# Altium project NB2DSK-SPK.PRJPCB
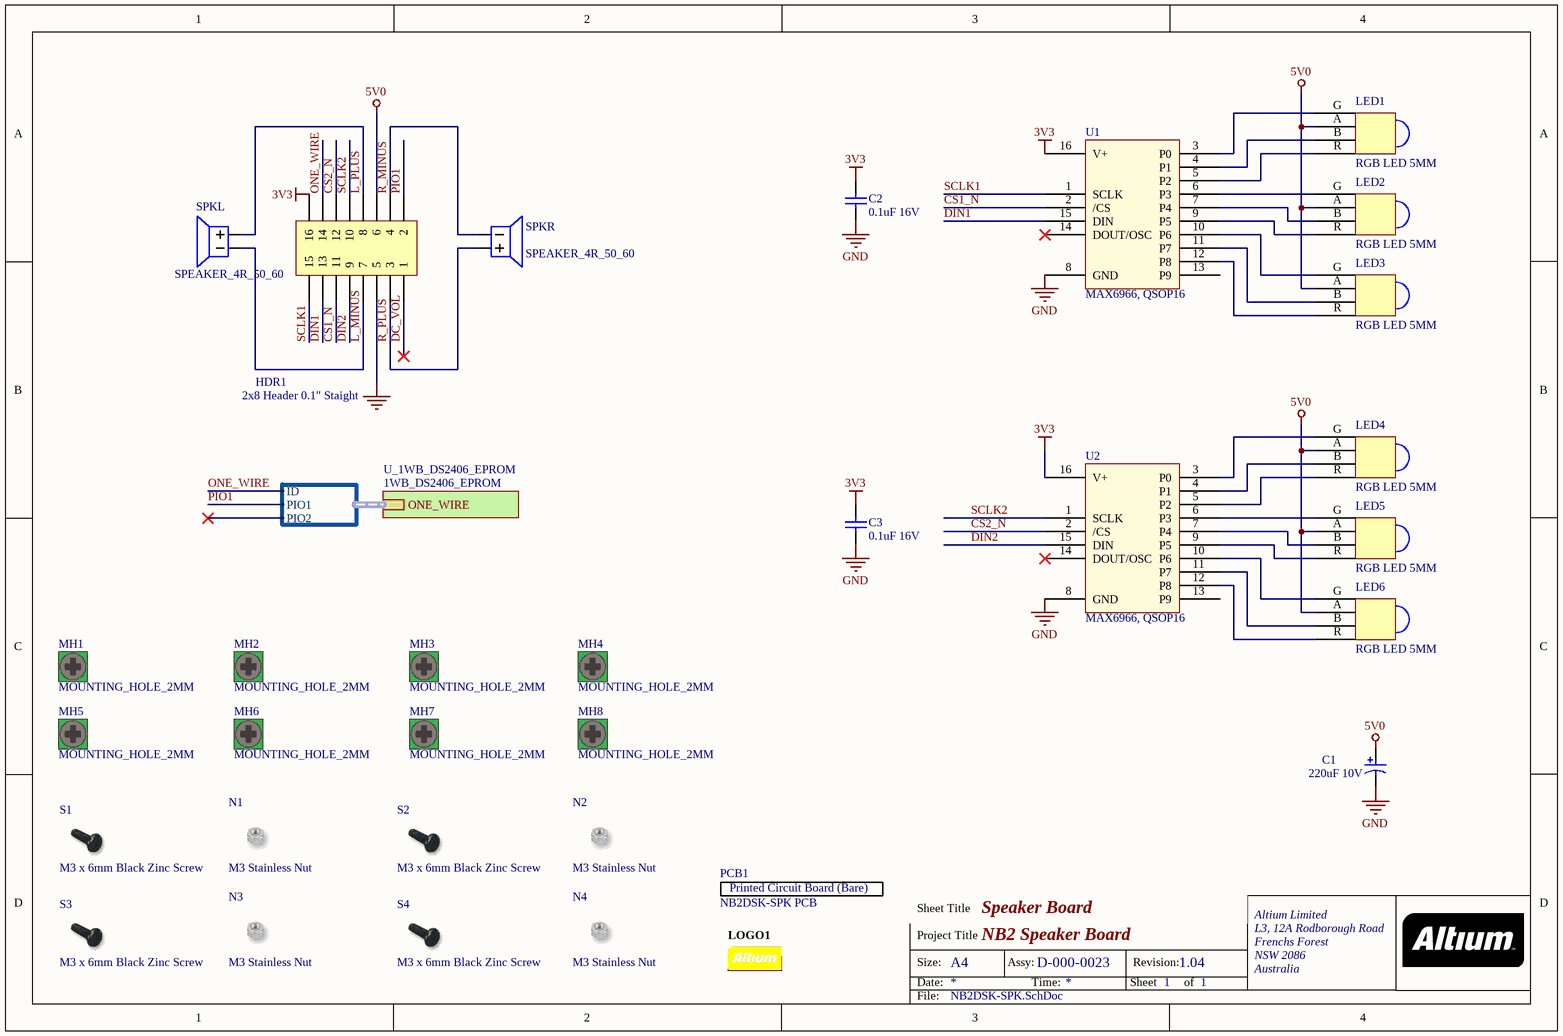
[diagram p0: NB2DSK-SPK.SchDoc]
ProjectAddress1: L3, 12A Rodborough Road; ProjectAddress2: Frenchs Forest; ProjectAddress3: NSW 2086; ProjectAddress4: Australia; ProjectAssyNum: D-000-0023; ProjectOrganization: Altium Limited; ProjectRevision: 1.04; ProjectTitle: NB2 Speaker Board; ProjectTotalSheets: 1
1 sheet, 32 parts. Net scope: hierarchical (ports join the sheet entries above them; power ports are global).
Board file: NB2DSK-SPK.PcbDoc

## Sheet NB2DSK-SPK.SchDoc: Speaker Board
size A4; SheetNumber: 1; SheetTotal: 1; PageSetup: Record=PageOptions|CenterHorizontal=True|CenterVertical=True|PrintScale=0.97|XCorrection=1.00|YCorrection=1.00|PrintKind=1|BorderSize=5000000|LeftOffset=0|BottomOffset=0|Orientation=2|PaperLength=1000|PaperWidth=1000|Scale=100|PaperSource=7|PrintQuality=-4|MediaType=1|DitherType=10|PaperKind=A4 (210 x 297 mm)|PrintScaleMode=1

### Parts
C1  220uF 10V  [CAPC7343-STAR]
C2  0.1uF 16V  [CAPC1005-STAR]
C3  0.1uF 16V  [CAPC1005-STAR]
HDR1  2x8 Header 0.1" Staight  [HDR2X8]
LED1  RGB LED 5MM  [LED-RGB-5MM-RA]
LED2  RGB LED 5MM  [LED-RGB-5MM-RA]
LED3  RGB LED 5MM  [LED-RGB-5MM-RA]
LED4  RGB LED 5MM  [LED-RGB-5MM-RA]
LED5  RGB LED 5MM  [LED-RGB-5MM-RA]
LED6  RGB LED 5MM  [LED-RGB-5MM-RA]
LOGO1  Altium  [Logo-Altium]  (value not drawn)  (no BOM)
MH1  MOUNTING_HOLE_2MM  [MOUNTING_HOLE_2MM]  (no BOM)
MH2  MOUNTING_HOLE_2MM  [MOUNTING_HOLE_2MM]  (no BOM)
MH3  MOUNTING_HOLE_2MM  [MOUNTING_HOLE_2MM]  (no BOM)
MH4  MOUNTING_HOLE_2MM  [MOUNTING_HOLE_2MM]  (no BOM)
MH5  MOUNTING_HOLE_2MM  [MOUNTING_HOLE_2MM]  (no BOM)
MH6  MOUNTING_HOLE_2MM  [MOUNTING_HOLE_2MM]  (no BOM)
MH7  MOUNTING_HOLE_2MM  [MOUNTING_HOLE_2MM]  (no BOM)
MH8  MOUNTING_HOLE_2MM  [MOUNTING_HOLE_2MM]  (no BOM)
N1  M3 Stainless Nut  (mechanical)
N2  M3 Stainless Nut  (mechanical)
N3  M3 Stainless Nut  (mechanical)
N4  M3 Stainless Nut  (mechanical)
PCB1  NB2DSK-SPK PCB  (mechanical)
S1  M3 x 6mm Black Zinc Screw  (mechanical)
S2  M3 x 6mm Black Zinc Screw  (mechanical)
S3  M3 x 6mm Black Zinc Screw  (mechanical)
S4  M3 x 6mm Black Zinc Screw  (mechanical)
SPKL  SPEAKER_4R_50_60  [SPEAKER_4R_50_60]
SPKR  SPEAKER_4R_50_60  [SPEAKER_4R_50_60]
U1  MAX6966, QSOP16  [QSOP16]
U2  MAX6966, QSOP16  [QSOP16]

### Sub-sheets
U_1WB_DS2406_EPROM = 1WB_DS2406_EPROM (file not in this document): ONE_WIRE (harness ONE_WIRE)

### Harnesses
ONE_WIRE: ID, PIO2, PIO1

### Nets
3V3: C2.2 C3.2 HDR1.16 U1.16(V+) U2.16(V+)
5V0: C1.1 HDR1.6 LED1.A LED2.A LED3.A LED4.A LED5.A LED6.A
GND: C1.2 C2.1 C3.1 HDR1.5 U1.8(GND) U2.8(GND)
CS1_N: HDR1.11 U1.2(/CS)
CS2_N: HDR1.12 U2.2(/CS)
DC_VOL: HDR1.1
DIN1: HDR1.13 U1.15(DIN)
DIN2: HDR1.9 U2.15(DIN)
L_MINUS: HDR1.7 SPKL.2
L_PLUS: HDR1.8 SPKL.1
ONE_WIRE: HDR1.14 ; sheet U_1WB_DS2406_EPROM/ONE_WIRE.ID
PIO1: HDR1.2 ; sheet U_1WB_DS2406_EPROM/ONE_WIRE.PIO1
R_MINUS: HDR1.4 SPKR.2
R_PLUS: HDR1.3 SPKR.1
SCLK1: HDR1.15 U1.1(SCLK)
SCLK2: HDR1.10 U2.1(SCLK)
NetLED1_B: LED1.B U1.4(P1)
NetLED1_G: LED1.G U1.3(P0)
NetLED1_R: LED1.R U1.5(P2)
NetLED2_B: LED2.B U1.7(P4)
NetLED2_G: LED2.G U1.6(P3)
NetLED2_R: LED2.R U1.9(P5)
NetLED3_B: LED3.B U1.11(P7)
NetLED3_G: LED3.G U1.10(P6)
NetLED3_R: LED3.R U1.12(P8)
NetLED4_B: LED4.B U2.4(P1)
NetLED4_G: LED4.G U2.3(P0)
NetLED4_R: LED4.R U2.5(P2)
NetLED5_B: LED5.B U2.7(P4)
NetLED5_G: LED5.G U2.6(P3)
NetLED5_R: LED5.R U2.9(P5)
NetLED6_B: LED6.B U2.11(P7)
NetLED6_G: LED6.G U2.10(P6)
NetLED6_R: LED6.R U2.12(P8)

Not connected (* = marked no-connect by the designer): MH1 1; MH2 1; MH3 1; MH4 1; MH5 1; MH6 1; MH7 1; MH8 1; U1 13(P9) 14(DOUT/OSC)*; U2 13(P9) 14(DOUT/OSC)*

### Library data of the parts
C1 = D-101-0088: Capacitor, Tantalum, 220uF 10% 10V MCCT-D (7343-31); Polarity: Polarized
C2 C3 = D-101-0080: Capacitor, Ceramic, 0.1uF 10% 16V 0402 (1005) X7R; Polarity: Non-Polarized
HDR1 = D-300-0041: Header, BOX 2x8, 0.1", Straight, Raised; Max Current: mA
LED1-LED6 = D-153-0001: LED, RGB, 5mm, 540R2GBC-CA, Common Anode; Brightness: 1500 mcd; Peak Wave Length: nm
LOGO1 = D-000-0003: Altium Logo for PCB
MH1-MH8 = MOUNTING_HOLE_2MM: 2mm Diameter Mounting Hole
N1-N4 = D-008-0022
PCB1 = D-000-0015: PCB, NB2 Speaker Board (NB2DSK-SPK)
S1-S4 = D-008-0012: M3 Black-Zinc Cross-Recess Pan-Head Machine Screw 6mm long
SPKL SPKR = D-003-0001: Speaker, 4 Omh 3W 50mm Cone 60mm Body
U1 U2 = D-243-0001: MAX6966, 10 port Constant Current LED Driver, SPI; Supply Voltage: mV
